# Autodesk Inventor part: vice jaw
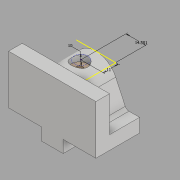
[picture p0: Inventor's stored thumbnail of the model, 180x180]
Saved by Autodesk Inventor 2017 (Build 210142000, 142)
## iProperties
Created: 2016-03
Part Number: vice jaw
Material: Generic
Document SubType Name: Modeling
Designer: Sandeep
Density: 1 g/cm^3
Appearance: Default
Author: Sandeep
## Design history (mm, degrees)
sketch "Sketch1"
  geometry: L1 (0, 0)-(-32, 0); L2 (-32, 0)-(-32, 36); L3 (-32, 36)-(-22, 36); L4 (-22, 36)-(-22, 10); L5 (-22, 10)-(0, 10); L6 (0, 10)-(0, 0)
  constraints: 12 end point, 5 perpendicular, 1 horizontal
  dimensions: "d0" = 36 distance between parallel lines of L1 L3; "d1" = 32 distance of L1.start L1.end; "d2" = 10 distance of L5.end L1.start; "d3" = 10 distance of L2.end L3.end
extrude "Extrusion1" new body sketch "Sketch1" stored distance "d4" = 64; taper "d5" = 0 deg
sketch "Sketch2"
  geometry: L1 (64, 10)-(64, 0) reference; L2 (64, 10)-(64, 0); L3 (64, 0)-(54.317, 0); L4 (64, 0)-(0, 0) reference; L5 (54.317, 0)-(46.501, -16.762); L6 (0, 0)-(0, 10); L7 (0, 10)-(64, 10); L8 (64, -26)-(0, -26) reference; L9 (0, 0)-(9.683, 0); L10 (32, 10)-(32, -39.451); L11 (9.683, 0)-(17.499, -16.762); A1 r 16 centre (32, -10) between (17.499, -16.762) and (46.501, -16.762); 1 further point
  constraints: 16 end point, 3 point on line, 2 collinear, 2 perpendicular, 2 point on circle, 2 symmetric about line, 2 tangent, 1 centre point, 1 coincident, 1 vertical
  dimensions: "d8" = 16 radius of A1; "d9" = 50 deg angle of L11 L5
extrude "Extrusion2" join sketch "Sketch2" stored distance "d10" = 32; taper "d11" = 0 deg
fillet "Fillet1" dims "d12" = 3
sketch "Sketch3"
  geometry: L1 (40, 0)-(40, 9); L2 (40, 9)-(24, 9); L3 (24, 9)-(24, 0); L4 (24, 0)-(40, 0); L5 (0, 0)-(64, 0) reference; L6 (32, 0)-(32, -54.171)
  constraints: 10 end point, 2 perpendicular, 2 vertical, 1 collinear, 1 point on line, 1 other
  dimensions: "d13" = 16 distance between parallel lines of L3 L1; "d14" = 9 distance of L2.end L3.end
extrude "Extrusion3" join sketch "Sketch3" stored distance "d15" = 32; taper "d16" = 0 deg
sketch "Sketch4"
  geometry: L1 (-24, 19)-(-40, 19) reference; L2 (-32, 19)-(-32, -29.453); C1 r 6 at (-32, -10); A1 r 16 centre (-32, -10) between (-46.501, -16.762) and (-17.499, -16.762) reference; 1 further point
  constraints: 2 end point, 1 centre point, 1 concentric, 1 midpoint, 1 point on line, 1 vertical
  dimensions: "d17" = 12 diameter of C1
extrude "Extrusion4" cut sketch "Sketch4" distance "d18" = 24; taper "d19" = 0 deg
sketch "Sketch6"
  geometry: 1 further point
workplane "Work Plane1"
sketch "Sketch7"
  geometry: L1 (14.501, 0)-(-14.501, 0) reference; L2 (14.501, 0)-(14.501, -22) reference; C1 r 5 at (0, -11); 1 further point
  constraints: 1 centre point
  dimensions: "d22" = 10 diameter of C1; "d23" = 11 distance from line of L1 C1.centre; "d24" = 14.50092 distance from line of C1.centre L2
workplane "Work Plane2"
hole "Hole1" diameter "d37" = 4.917; stored, may be unused: countersink angle "d41" = 90 deg, drill point angle "d43" = 118 deg; dims "d35" = 8, "d36" = 8, "d38" = 12, "d39" = 4, "d40" = 2, "d42" = 16
hole "Hole2" diameter "d46" = 4.917; stored, may be unused: countersink angle "d50" = 90 deg, drill point angle "d52" = 118 deg; dims "d44" = 8, "d45" = 8, "d47" = 12, "d48" = 4, "d49" = 2, "d51" = 16
hole "Hole3" diameter "d55" = 4.917; stored, may be unused: countersink angle "d59" = 82 deg, drill point angle "d61" = 118 deg; dims "d53" = 20, "d54" = 32, "d56" = 12, "d57" = 12, "d58" = 5, "d60" = 17.1
sketch "Sketch10"
  geometry: 1 further point
body "Solid1"
